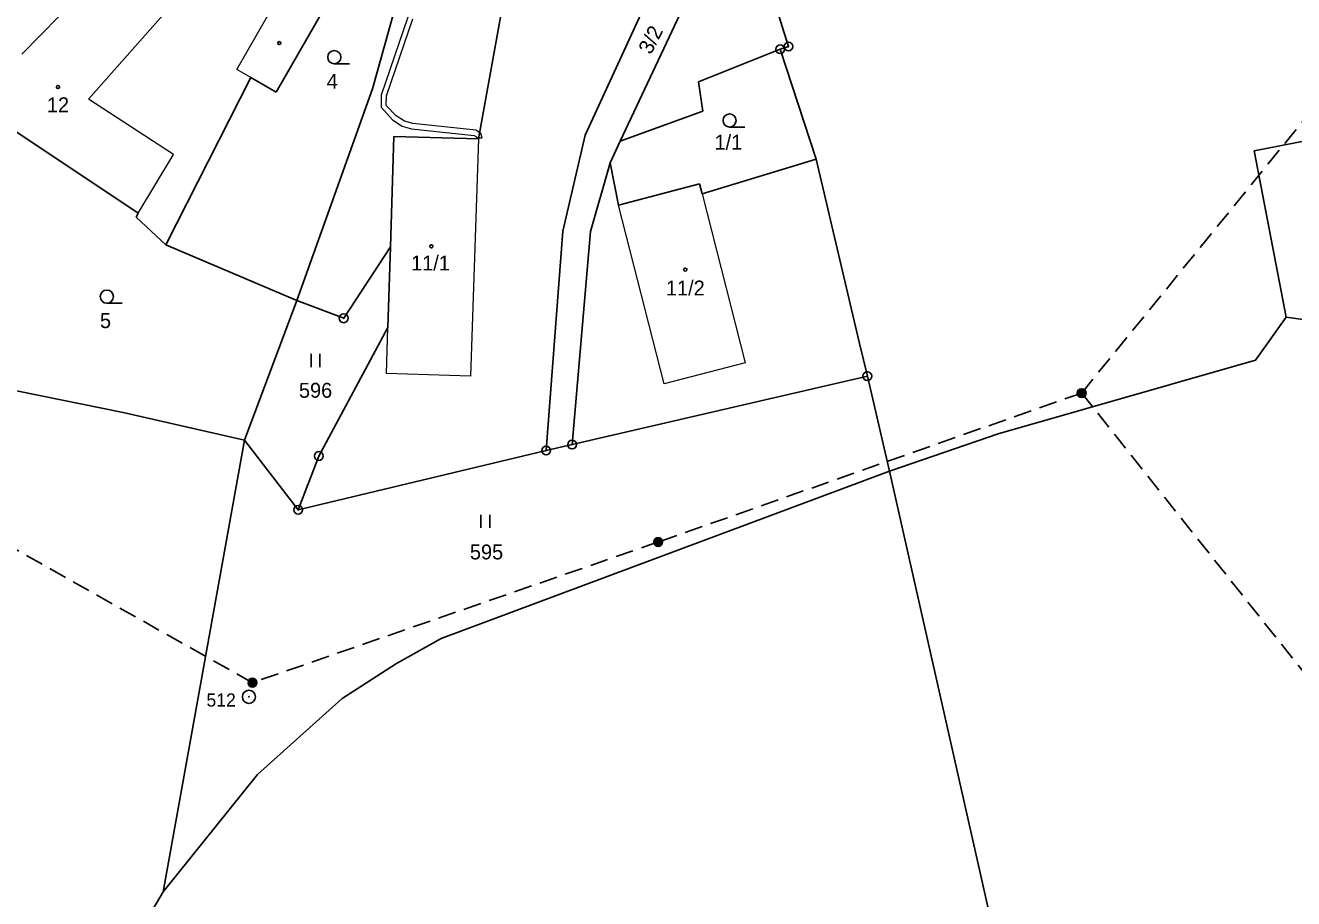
# Model space of a CAD drawing. Extents: x -653193 to -651624, y -1092017 to -1090260.
# Drawn here: x -652971.4 to -652826.7, y -1091442.9 to -1091343.3 of the extents above; entities that cross this region are included whole.
import ezdxf
from ezdxf.enums import TextEntityAlignment as Align

# ---------------------------------------------------------------- set-up
doc = ezdxf.new("R2010")
doc.units = 0
doc.header["$LTSCALE"] = 0.68
doc.linetypes.add('MEDIUM_DASHED', pattern=[4.5, 3, -1.5])
for name, color, linetype, lineweight in [('1', 7, 'Continuous', 25), ('13', 7, 'Continuous', 13), ('3', 7, 'Continuous', 25), ('4', 7, 'Continuous', 13), ('5', 7, 'Continuous', 25), ('6', 7, 'Continuous', 25), ('8', 7, 'Continuous', 25)]:
    doc.layers.add(name, color=color, linetype=linetype, lineweight=lineweight)
doc.layers.add('2', color=7, linetype='Continuous')

msp = doc.modelspace()

# ---------------------------------------------------------------- linework, layer by layer
at = {"layer": '1'}
for p, q in [((-652922.28, -1091316.16), (-652931.8, -1091350.57)), ((-652887.91, -1091323.32), (-652903.57, -1091356.54)), ((-652956.81, -1091331.27), (-652971.83, -1091346.61)), ((-652884.37, -1091345.73), (-652888.99, -1091331.06)), ((-652907.57, -1091355.84), (-652896.68, -1091332.18)), ((-652919.74, -1091356.26), (-652916.48, -1091338.19)), ((-652937.42, -1091341.55), (-652942.81, -1091350.95)), ((-652885.32, -1091346.04), (-652894.64, -1091349.74)), ((-652885.32, -1091346.04), (-652884.37, -1091345.73)), ((-652881.2, -1091358.57), (-652885.32, -1091346.04)), ((-652945.71, -1091349.26), (-652955.39, -1091368.35)), ((-652942.81, -1091350.95), (-652945.71, -1091349.26)), ((-652931.8, -1091350.57), (-652940.45, -1091374.69)), ((-652894.12, -1091353.09), (-652894.64, -1091349.74)), ((-652958.56, -1091364.74), (-652975.06, -1091353.74)), ((-652903.57, -1091356.54), (-652894.12, -1091353.09)), ((-652831.25, -1091357.64), (-652808.58, -1091353.15)), ((-652929.77, -1091368.59), (-652929.37, -1091355.98)), ((-652929.37, -1091355.98), (-652919.74, -1091356.26)), ((-652910.11, -1091366.8), (-652907.57, -1091355.84)), ((-652903.57, -1091356.54), (-652904.72, -1091358.98)), ((-652827.61, -1091376.61), (-652831.25, -1091357.64)), ((-652904.72, -1091358.98), (-652906.95, -1091366.84)), ((-652903.77, -1091363.81), (-652904.72, -1091358.98)), ((-652881.2, -1091358.57), (-652894.22, -1091362.52)), ((-652876.25, -1091379.6), (-652881.2, -1091358.57)), ((-652903.77, -1091363.81), (-652894.5, -1091361.41)), ((-652894.5, -1091361.41), (-652894.22, -1091362.52)), ((-652958.56, -1091364.74), (-652958.79, -1091365.18)), ((-652958.79, -1091365.18), (-652955.39, -1091368.35)), ((-652912.01, -1091391.82), (-652910.11, -1091366.8)), ((-652906.95, -1091366.84), (-652909.05, -1091391.14)), ((-652940.45, -1091374.69), (-652955.39, -1091368.35)), ((-652935.1, -1091376.73), (-652929.77, -1091368.59)), ((-652929.77, -1091368.59), (-652930.06, -1091377.79)), ((-652946.43, -1091390.64), (-652940.45, -1091374.69)), ((-652940.45, -1091374.69), (-652935.1, -1091376.73)), ((-652827.61, -1091376.61), (-652831.08, -1091381.52)), ((-652768.36, -1091384.4), (-652827.61, -1091376.61)), ((-652930.06, -1091377.79), (-652937.93, -1091392.44)), ((-652875.37, -1091383.33), (-652876.25, -1091379.6)), ((-652984.56, -1091382.58), (-652960.27, -1091387.47)), ((-652831.08, -1091381.52), (-652860.44, -1091389.93)), ((-652909.05, -1091391.14), (-652875.37, -1091383.33)), ((-652872.86, -1091394.17), (-652875.37, -1091383.33)), ((-652960.27, -1091387.47), (-652946.43, -1091390.64)), ((-652860.44, -1091389.93), (-652872.86, -1091394.17)), ((-652955.7, -1091442.14), (-652946.43, -1091390.64)), ((-652946.43, -1091390.64), (-652940.29, -1091398.58)), ((-652912.01, -1091391.82), (-652909.05, -1091391.14)), ((-652940.29, -1091398.58), (-652912.01, -1091391.82)), ((-652937.93, -1091392.44), (-652940.29, -1091398.58)), ((-652843.58, -1091523.54), (-652872.86, -1091394.17)), ((-652929.06, -1091416.11), (-652935.29, -1091420.11)), ((-652935.29, -1091420.11), (-652944.94, -1091428.79)), ((-652944.94, -1091428.79), (-652955.7, -1091442.14)), ((-652958.72, -1091447.26), (-652955.7, -1091442.14))]:
    msp.add_line(p, q, dxfattribs=at)
msp.add_lwpolyline([(-652872.86, -1091394.17), (-652924, -1091413.26), (-652929.06, -1091416.11)], dxfattribs=at)
at = {"layer": '13'}
msp.add_lwpolyline([(-652927.78, -1091342.38), (-652930.82, -1091351.26), (-652930.84, -1091352.66), (-652929.53, -1091354.1), (-652928.44, -1091354.81), (-652927.35, -1091355.12), (-652920.21, -1091355.86), (-652919.97, -1091356.02), (-652919.94, -1091356.14), (-652919.78, -1091356.14), (-652919.32, -1091356.16), (-652919.45, -1091355.64), (-652920.01, -1091355.28), (-652927.23, -1091354.52), (-652928.18, -1091354.25), (-652929.13, -1091353.64), (-652930.24, -1091352.44), (-652930.22, -1091351.36), (-652927.2, -1091342.56)], dxfattribs=at)
at = {"layer": '3'}
for p, q in [((-652936.173, -1091347.69), (-652934.423, -1091347.69)), ((-652891.083, -1091354.91), (-652889.333, -1091354.91)), ((-652962.113, -1091375.01), (-652960.363, -1091375.01)), ((-652938.811, -1091382.3), (-652938.811, -1091380.8)), ((-652937.81, -1091382.3), (-652937.81, -1091380.8)), ((-652919.451, -1091400.65), (-652919.451, -1091399.15)), ((-652918.45, -1091400.65), (-652918.45, -1091399.15))]:
    msp.add_line(p, q, dxfattribs=at)
for centre in [(-652936.1729, -1091346.9398), (-652891.0829, -1091354.1598), (-652962.1129, -1091374.2598)]:
    msp.add_circle(centre, 0.75, dxfattribs=at)
at = {"layer": '4'}
for p, q in [((-652964.2, -1091351.74), (-652950.87, -1091336.63)), ((-652947.29, -1091348.34), (-652941.92, -1091338.96)), ((-652945.71, -1091349.26), (-652947.29, -1091348.34)), ((-652954.51, -1091358.04), (-652964.2, -1091351.74)), ((-652919.74, -1091356.26), (-652920.65, -1091383.35)), ((-652958.56, -1091364.74), (-652954.51, -1091358.04)), ((-652898.56, -1091384.2), (-652903.77, -1091363.81)), ((-652894.22, -1091362.52), (-652889.3, -1091381.82)), ((-652930.23, -1091383.03), (-652930.06, -1091377.79)), ((-652889.3, -1091381.82), (-652898.56, -1091384.2)), ((-652920.65, -1091383.35), (-652930.23, -1091383.03))]:
    msp.add_line(p, q, dxfattribs=at)
at = {"layer": '5'}
for centre in [(-652942.4468, -1091345.3392), (-652967.6968, -1091350.3492), (-652925.0968, -1091368.5192), (-652896.1368, -1091371.1792)]:
    msp.add_circle(centre, 0.175, dxfattribs=at)
at = {"layer": '6', "linetype": 'MEDIUM_DASHED'}
for p, q in [((-652850.92, -1091385.26), (-652818.4, -1091345.29)), ((-652850.92, -1091385.26), (-652899.22, -1091402.25)), ((-652819.26, -1091425.08), (-652850.92, -1091385.26)), ((-652945.51, -1091418.3), (-652996.08, -1091389.81)), ((-652899.22, -1091402.25), (-652945.51, -1091418.3))]:
    msp.add_line(p, q, dxfattribs=at)
at = {"layer": '6'}
for centre, radius in [((-652850.9234, -1091385.2599), 0.5), ((-652850.9234, -1091385.2599), 0.4), ((-652850.9234, -1091385.2599), 0.3), ((-652850.9234, -1091385.2599), 0.2), ((-652850.9234, -1091385.2599), 0.1), ((-652899.2234, -1091402.2499), 0.5), ((-652899.2234, -1091402.2499), 0.4), ((-652899.2234, -1091402.2499), 0.3), ((-652899.2234, -1091402.2499), 0.2), ((-652899.2234, -1091402.2499), 0.1), ((-652945.5134, -1091418.2999), 0.5), ((-652945.5134, -1091418.2999), 0.4), ((-652945.5134, -1091418.2999), 0.3), ((-652945.5134, -1091418.2999), 0.2), ((-652945.5134, -1091418.2999), 0.1)]:
    msp.add_circle(centre, radius, dxfattribs=at)
at = {"layer": '8'}
for centre, radius in [((-652885.32, -1091346.0399), 0.5), ((-652885.32, -1091346.0399), 0.0303), ((-652884.37, -1091345.7299), 0.5), ((-652884.37, -1091345.7299), 0.0303), ((-652935.1, -1091376.7299), 0.5), ((-652935.1, -1091376.7299), 0.0303), ((-652875.37, -1091383.3299), 0.5), ((-652875.37, -1091383.3299), 0.0303), ((-652912.01, -1091391.8199), 0.5), ((-652909.05, -1091391.1399), 0.5), ((-652909.05, -1091391.1399), 0.0303), ((-652937.93, -1091392.4399), 0.5), ((-652937.93, -1091392.4399), 0.0303), ((-652912.01, -1091391.8199), 0.0303), ((-652940.29, -1091398.5799), 0.5), ((-652940.29, -1091398.5799), 0.0303), ((-652945.91, -1091419.9098), 0.75), ((-652945.91, -1091419.9098), 0.03)]:
    msp.add_circle(centre, radius, dxfattribs=at)

# ---------------------------------------------------------------- texts
at = {"layer": '2'}
msp.add_text('3/2', height=1.7, rotation=63, dxfattribs=at).set_placement((-652899.3404, -1091345.3254), align=Align.CENTER)
for s, p in [('4', (-652936.41, -1091350.545)), ('12', (-652967.689, -1091353.225)), ('1/1', (-652891.22, -1091357.495)), ('11/1', (-652925.199, -1091371.275)), ('11/2', (-652896.129, -1091374.125)), ('5', (-652962.27, -1091377.845)), ('596', (-652938.309, -1091385.795)), ('595', (-652918.809, -1091404.235))]:
    msp.add_text(s, height=1.7, dxfattribs=at).set_placement(p, align=Align.CENTER)
at = {"layer": '8'}
msp.add_text('512', height=1.5, dxfattribs=at).set_placement((-652947.409, -1091421.027), align=Align.RIGHT)

doc.saveas('drawing.dxf')
